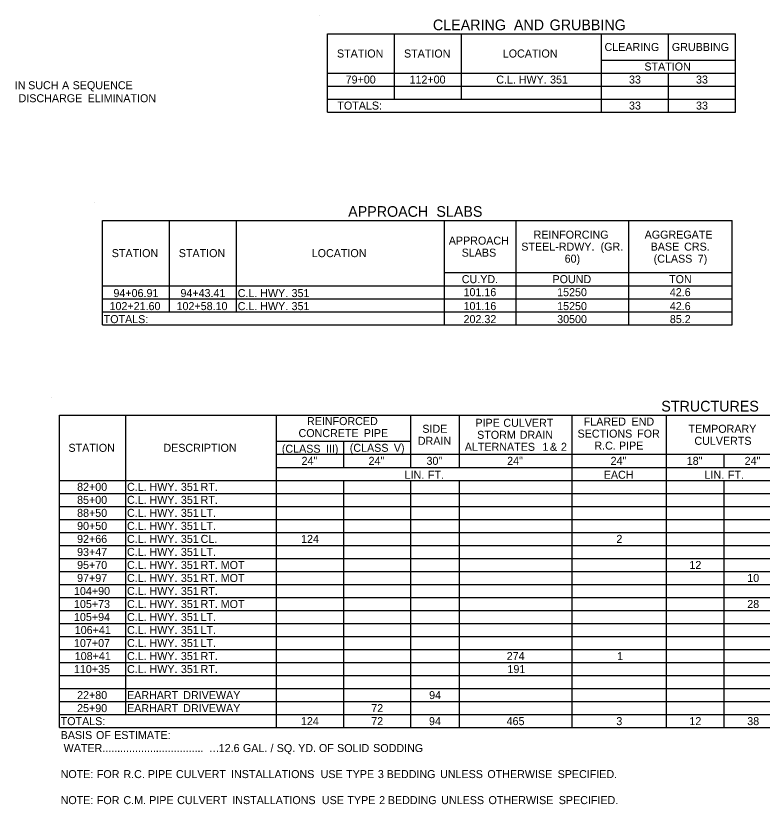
# Model space of a CAD drawing. Extents: x 1197542 to 1207068, y 230488 to 237324.
# Drawn here: x 1200309 to 1200869, y 231751 to 232342 of the extents above; entities that cross this region are included whole.
import ezdxf

# ---------------------------------------------------------------- set-up
doc = ezdxf.new("R2010")
doc.units = 0
doc.layers.add('Default', color=7, linetype='Continuous')

msp = doc.modelspace()

# ---------------------------------------------------------------- linework, layer by layer
at = {"layer": 'Default'}
for p, q in [((1200537.11, 232342.15), (1200537.11, 232342.15)), ((1200542.96, 232328.5), (1200848.62, 232328.5)), ((1200542.96, 232270), (1200542.96, 232328.5)), ((1200542.96, 232270), (1200542.96, 232328.5)), ((1200593.17, 232279.75), (1200593.17, 232328.5)), ((1200643.38, 232279.75), (1200643.38, 232328.5)), ((1200748.2, 232270), (1200748.2, 232328.5)), ((1200798.41, 232309), (1200798.41, 232328.5)), ((1200848.62, 232270), (1200848.62, 232328.5)), ((1200848.62, 232309), (1200848.62, 232328.5)), ((1200748.2, 232309), (1200848.62, 232309)), ((1200748.2, 232279.75), (1200748.2, 232309)), ((1200542.96, 232299.25), (1200848.62, 232299.25)), ((1200593.17, 232279.75), (1200593.17, 232299.25)), ((1200643.38, 232279.75), (1200643.38, 232299.25)), ((1200798.41, 232270), (1200798.41, 232299.25)), ((1200798.41, 232270), (1200798.41, 232299.25)), ((1200848.62, 232279.75), (1200848.62, 232299.25)), ((1200542.96, 232289.5), (1200848.62, 232289.5)), ((1200542.96, 232279.75), (1200848.62, 232279.75)), ((1200643.38, 232279.75), (1200848.62, 232279.75)), ((1200542.96, 232270), (1200848.62, 232270)), ((1200368.37, 232202.35), (1200368.37, 232202.35)), ((1200374.22, 232188.7), (1200846.12, 232188.7)), ((1200374.22, 232110.7), (1200374.22, 232188.7)), ((1200374.22, 232110.7), (1200374.22, 232188.7)), ((1200424.44, 232120.45), (1200424.44, 232188.7)), ((1200474.65, 232120.45), (1200474.65, 232188.7)), ((1200630.65, 232110.7), (1200630.65, 232188.7)), ((1200684.27, 232110.7), (1200684.27, 232188.7)), ((1200768.61, 232110.7), (1200768.61, 232188.7)), ((1200846.12, 232110.7), (1200846.12, 232188.7)), ((1200630.65, 232149.7), (1200846.12, 232149.7)), ((1200684.27, 232110.7), (1200684.27, 232149.7)), ((1200768.61, 232110.7), (1200768.61, 232149.7)), ((1200846.12, 232110.7), (1200846.12, 232149.7)), ((1200374.22, 232139.95), (1200846.12, 232139.95)), ((1200424.44, 232120.45), (1200424.44, 232139.95)), ((1200474.65, 232120.45), (1200474.65, 232139.95)), ((1200630.65, 232110.7), (1200630.65, 232139.95)), ((1200374.22, 232130.2), (1200846.12, 232130.2)), ((1200374.22, 232120.45), (1200846.12, 232120.45)), ((1200374.22, 232110.7), (1200846.12, 232110.7)), ((1200336.15, 232056.51), (1200336.15, 232056.51)), ((1200342, 232042.86), (1201314.56, 232042.86)), ((1200342, 231808.86), (1200342, 232042.86)), ((1200342, 231808.86), (1200342, 232042.86)), ((1200391.72, 231818.61), (1200391.72, 232042.86)), ((1200504.82, 231808.86), (1200504.82, 232042.86)), ((1200605.25, 232003.86), (1200605.25, 232042.86)), ((1200641.81, 232003.86), (1200641.81, 232042.86)), ((1200726.15, 231808.86), (1200726.15, 232042.86)), ((1200796.83, 231808.86), (1200796.83, 232042.86)), ((1200796.83, 231808.86), (1200796.83, 232042.86)), ((1200504.82, 232023.36), (1200605.25, 232023.36)), ((1200555.03, 232003.86), (1200555.03, 232023.36)), ((1200555.03, 232003.86), (1200555.03, 232023.36)), ((1200504.82, 232013.61), (1200555.03, 232013.61)), ((1200555.03, 232013.61), (1200952.35, 232013.61)), ((1200605.25, 232003.86), (1200605.25, 232013.61)), ((1200641.81, 232003.86), (1200641.81, 232013.61)), ((1200726.15, 231808.86), (1200726.15, 232013.61)), ((1200840.22, 232003.86), (1200840.22, 232013.61)), ((1200840.22, 232003.86), (1200840.22, 232013.61)), ((1200504.82, 232003.86), (1200952.35, 232003.86)), ((1200342, 231994.11), (1201314.56, 231994.11)), ((1200391.72, 231818.61), (1200391.72, 231994.11)), ((1200555.03, 231808.86), (1200555.03, 231994.11)), ((1200555.03, 231808.86), (1200555.03, 231994.11)), ((1200605.25, 231808.86), (1200605.25, 231994.11)), ((1200605.25, 231808.86), (1200605.25, 231994.11)), ((1200641.81, 231808.86), (1200641.81, 231994.11)), ((1200641.81, 231808.86), (1200641.81, 231994.11)), ((1200840.22, 231808.86), (1200840.22, 231994.11)), ((1200840.22, 231808.86), (1200840.22, 231994.11)), ((1200342, 231984.36), (1201314.56, 231984.36)), ((1200342, 231974.61), (1201314.56, 231974.61)), ((1200342, 231964.86), (1201314.56, 231964.86)), ((1200342, 231955.11), (1201314.56, 231955.11)), ((1200342, 231945.36), (1201314.56, 231945.36)), ((1200342, 231935.61), (1201314.56, 231935.61)), ((1200342, 231925.86), (1201314.56, 231925.86)), ((1200342, 231916.11), (1201314.56, 231916.11)), ((1200342, 231906.36), (1201314.56, 231906.36)), ((1200342, 231896.61), (1201314.56, 231896.61)), ((1200342, 231886.86), (1201314.56, 231886.86)), ((1200342, 231877.11), (1201314.56, 231877.11)), ((1200342, 231867.36), (1201314.56, 231867.36)), ((1200342, 231857.61), (1201314.56, 231857.61)), ((1200342, 231847.86), (1201314.56, 231847.86)), ((1200342, 231838.11), (1201314.56, 231838.11)), ((1200342, 231828.36), (1201314.56, 231828.36)), ((1200342, 231818.61), (1201101.52, 231818.61)), ((1200342, 231818.61), (1200504.82, 231818.61)), ((1200342, 231808.86), (1201314.56, 231808.86))]:
    msp.add_line(p, q, dxfattribs=at)

# ---------------------------------------------------------------- texts
for s, height, p in [('CLEARING', 8, (1200621.91, 232331.33)), (' AND', 8, (1200679.61, 232331.33)), (' GRUBBING', 8, (1200706.38, 232331.33)), ('CLEARING', 6, (1200750.5, 232315.75)), ('GRUBBING', 6, (1200800.95, 232315.75)), ('STATION', 6, (1200550, 232310.88)), ('STATION', 6, (1200600.22, 232310.88)), ('LOCATION', 6, (1200674.24, 232310.88)), ('STATION', 6, (1200780.35, 232301.13)), ('79+00', 6, (1200556.5, 232291.38)), ('112+00', 6, (1200604.38, 232291.38)), ('C.L.', 6, (1200669.35, 232291.38)), (' HWY.', 6, (1200683.98, 232291.38)), (' 351', 6, (1200707.47, 232291.38)), ('33', 6, (1200768.83, 232291.38)), ('33', 6, (1200819.04, 232291.38)), (' IN', 6, (1200306.36, 232287.11)), (' SUCH', 6, (1200316.38, 232287.11)), (' A', 6, (1200341.79, 232287.11)), (' SEQUENCE', 6, (1200349.73, 232287.11)), (' DISCHARGE', 6, (1200309.22, 232277.36)), (' ELIMINATION', 6, (1200360.95, 232277.36)), ('TOTALS:', 6, (1200550.31, 232271.88)), ('33', 6, (1200768.82, 232271.88)), ('33', 6, (1200819.04, 232271.88)), ('APPROACH', 8, (1200558.39, 232191.53)), (' SLABS', 8, (1200621.51, 232191.53)), ('REINFORCING', 6, (1200697.35, 232175.2)), ('AGGREGATE', 6, (1200780.56, 232175.2)), ('APPROACH', 6, (1200633.79, 232170.7)), ('STEEL-RDWY.', 6, (1200688.13, 232166.2)), (' (GR.', 6, (1200745.31, 232166.2)), ('BASE', 6, (1200785.04, 232166.2)), (' CRS.', 6, (1200807.92, 232166.2)), ('STATION', 6, (1200381.27, 232161.33)), ('STATION', 6, (1200431.48, 232161.33)), ('LOCATION', 6, (1200531.1, 232161.33)), ('SLABS', 6, (1200643.46, 232161.7)), ('60)', 6, (1200720.61, 232157.2)), ('(CLASS', 6, (1200787.3, 232157.2)), (' 7)', 6, (1200818.09, 232157.2)), ('CU.YD.', 6, (1200643.54, 232141.83)), ('POUND', 6, (1200711.51, 232141.83)), ('TON', 6, (1200798.86, 232141.83)), ('94+06.91', 6, (1200382.51, 232131.4)), ('94+43.41', 6, (1200432.72, 232131.4)), ('C.L.', 6, (1200475.62, 232131.4)), (' HWY.', 6, (1200490.26, 232131.4)), (' 351', 6, (1200513.75, 232131.4)), ('101.16', 6, (1200644.84, 232132.08)), ('15250', 6, (1200714.99, 232132.08)), ('42.6', 6, (1200799.4, 232132.08)), ('102+21.60', 6, (1200379.61, 232121.65)), ('102+58.10', 6, (1200429.82, 232121.65)), ('C.L.', 6, (1200475.62, 232121.65)), (' HWY.', 6, (1200490.26, 232121.65)), (' 351', 6, (1200513.75, 232121.65)), ('101.16', 6, (1200644.84, 232121.65)), ('15250', 6, (1200714.99, 232121.65)), ('42.6', 6, (1200799.4, 232121.65)), ('TOTALS:', 6, (1200375.2, 232111.9)), ('202.32', 6, (1200644.86, 232111.9)), ('30500', 6, (1200715, 232111.9)), ('85.2', 6, (1200799.43, 232111.9)), ('STRUCTURES', 8, (1200793.03, 232045.68)), ('REINFORCED', 6, (1200527.53, 232035.51)), ('PIPE', 6, (1200653.76, 232034.23)), (' CULVERT', 6, (1200672.45, 232034.23)), ('FLARED', 6, (1200734.89, 232035.13)), (' END', 6, (1200768.47, 232035.13)), ('CONCRETE', 6, (1200521.21, 232026.51)), (' PIPE', 6, (1200567.84, 232026.51)), ('SIDE', 6, (1200613.95, 232029.73)), ('STORM', 6, (1200655.04, 232025.23)), (' DRAIN', 6, (1200684.71, 232025.23)), ('SECTIONS', 6, (1200730.27, 232026.13)), (' FOR', 6, (1200772.72, 232026.13)), ('TEMPORARY', 6, (1200813.43, 232029.73)), ('DRAIN', 6, (1200610.59, 232020.73)), ('CULVERTS', 6, (1200817.83, 232020.73)), ('STATION', 6, (1200348.8, 232015.48)), ('DESCRIPTION', 6, (1200419.96, 232015.48)), ('(CLASS', 6, (1200508.7, 232014.81)), (' III)', 6, (1200539.49, 232014.81)), ('(CLASS', 6, (1200559.6, 232015.48)), (' V)', 6, (1200590.4, 232015.48)), ('ALTERNATES', 6, (1200645.78, 232016.23)), (' 1', 6, (1200701.73, 232016.23)), (' &', 6, (1200707.36, 232016.23)), (' 2', 6, (1200715.61, 232016.23)), ('R.C.', 6, (1200742.89, 232017.13)), (' PIPE', 6, (1200759.07, 232017.13)), ('24"', 6, (1200523.49, 232005.73)), ('24"', 6, (1200573.7, 232005.73)), ('30"', 6, (1200617.09, 232005.73)), ('24"', 6, (1200677.54, 232005.73)), ('24"', 6, (1200755.05, 232005.73)), ('18"', 6, (1200812.09, 232005.73)), ('24"', 6, (1200855.48, 232005.73)), ('LIN.', 6, (1200600.69, 231995.31)), (' FT.', 6, (1200615.95, 231995.31)), ('EACH', 6, (1200749.93, 231995.31)), ('LIN.', 6, (1200825.43, 231995.31)), (' FT.', 6, (1200840.69, 231995.31)), ('82+00', 6, (1200355.29, 231986.23)), ('C.L.', 6, (1200392.7, 231986.23)), (' HWY.', 6, (1200407.33, 231986.23)), (' 351', 6, (1200430.82, 231986.23)), (' RT.', 6, (1200445.58, 231986.23)), ('85+00', 6, (1200355.29, 231976.48)), ('C.L.', 6, (1200392.7, 231976.48)), (' HWY.', 6, (1200407.33, 231976.48)), (' 351', 6, (1200430.82, 231976.48)), (' RT.', 6, (1200445.58, 231976.48)), ('88+50', 6, (1200355.29, 231966.73)), ('C.L.', 6, (1200392.7, 231966.73)), (' HWY.', 6, (1200407.33, 231966.73)), (' 351', 6, (1200430.82, 231966.73)), (' LT.', 6, (1200445.58, 231966.73)), ('90+50', 6, (1200355.29, 231956.98)), ('C.L.', 6, (1200392.7, 231956.98)), (' HWY.', 6, (1200407.33, 231956.98)), (' 351', 6, (1200430.82, 231956.98)), (' LT.', 6, (1200445.58, 231956.98)), ('92+66', 6, (1200355.28, 231947.23)), ('C.L.', 6, (1200392.7, 231947.23)), (' HWY.', 6, (1200407.33, 231947.23)), (' 351', 6, (1200430.82, 231947.23)), (' CL.', 6, (1200445.58, 231947.23)), ('124', 6, (1200523.14, 231947.23)), ('2', 6, (1200759.38, 231947.23)), ('93+47', 6, (1200355.28, 231937.48)), ('C.L.', 6, (1200392.7, 231937.48)), (' HWY.', 6, (1200407.33, 231937.48)), (' 351', 6, (1200430.82, 231937.48)), (' LT.', 6, (1200445.58, 231937.48)), ('95+70', 6, (1200355.29, 231927.73)), ('C.L.', 6, (1200392.7, 231927.73)), (' HWY.', 6, (1200407.33, 231927.73)), (' 351', 6, (1200430.82, 231927.73)), (' RT.', 6, (1200445.58, 231927.73)), (' MOT', 6, (1200460.68, 231927.73)), ('12', 6, (1200814.09, 231927.73)), ('97+97', 6, (1200355.28, 231917.98)), ('C.L.', 6, (1200392.7, 231917.98)), (' HWY.', 6, (1200407.33, 231917.98)), (' 351', 6, (1200430.82, 231917.98)), (' RT.', 6, (1200445.58, 231917.98)), (' MOT', 6, (1200460.68, 231917.98)), ('10', 6, (1200857.46, 231917.98)), ('104+90', 6, (1200352.96, 231908.23)), ('C.L.', 6, (1200392.7, 231908.23)), (' HWY.', 6, (1200407.33, 231908.23)), (' 351', 6, (1200430.82, 231908.23)), (' RT.', 6, (1200445.58, 231908.23)), ('105+73', 6, (1200352.95, 231898.48)), ('C.L.', 6, (1200392.7, 231898.48)), (' HWY.', 6, (1200407.33, 231898.48)), (' 351', 6, (1200430.82, 231898.48)), (' RT.', 6, (1200445.58, 231898.48)), (' MOT', 6, (1200460.68, 231898.48)), ('28', 6, (1200857.44, 231898.48)), ('105+94', 6, (1200352.96, 231888.73)), ('C.L.', 6, (1200392.7, 231888.73)), (' HWY.', 6, (1200407.33, 231888.73)), (' 351', 6, (1200430.82, 231888.73)), (' LT.', 6, (1200445.58, 231888.73)), ('106+41', 6, (1200353.53, 231878.98)), ('C.L.', 6, (1200392.7, 231878.98)), (' HWY.', 6, (1200407.33, 231878.98)), (' 351', 6, (1200430.82, 231878.98)), (' LT.', 6, (1200445.58, 231878.98)), ('107+07', 6, (1200352.95, 231869.23)), ('C.L.', 6, (1200392.7, 231869.23)), (' HWY.', 6, (1200407.33, 231869.23)), (' 351', 6, (1200430.82, 231869.23)), (' LT.', 6, (1200445.58, 231869.23)), ('108+41', 6, (1200353.53, 231859.48)), ('C.L.', 6, (1200392.7, 231859.48)), (' HWY.', 6, (1200407.33, 231859.48)), (' 351', 6, (1200430.82, 231859.48)), (' RT.', 6, (1200445.58, 231859.48)), ('274', 6, (1200677.19, 231859.48)), ('1', 6, (1200759.93, 231859.48)), ('110+35', 6, (1200352.93, 231849.73)), ('C.L.', 6, (1200392.7, 231849.73)), (' HWY.', 6, (1200407.33, 231849.73)), (' 351', 6, (1200430.82, 231849.73)), (' RT.', 6, (1200445.58, 231849.73)), ('191', 6, (1200677.76, 231849.73)), ('22+80', 6, (1200355.29, 231830.23)), ('EARHART', 6, (1200392.7, 231830.23)), (' DRIVEWAY', 6, (1200432.59, 231830.23)), ('94', 6, (1200619.07, 231830.23)), ('25+90', 6, (1200355.29, 231820.48)), ('EARHART', 6, (1200392.7, 231820.48)), (' DRIVEWAY', 6, (1200432.59, 231820.48)), ('72', 6, (1200575.7, 231820.48)), ('TOTALS:', 6, (1200342.97, 231810.73)), ('124', 6, (1200523.03, 231810.73)), ('72', 6, (1200575.69, 231810.73)), ('94', 6, (1200618.96, 231810.73)), ('465', 6, (1200677.11, 231810.73)), ('3', 6, (1200759.34, 231810.73)), ('12', 6, (1200814.08, 231810.73)), ('38', 6, (1200857.44, 231810.73)), ('BASIS', 6, (1200342.97, 231800.31)), (' OF', 6, (1200367.23, 231800.31)), (' ESTIMATE:', 6, (1200380.82, 231800.31)), (' WATER..................................', 6, (1200342.97, 231790.56)), ('12.6', 6, (1200461.38, 231790.56)), (' GAL.', 6, (1200477.31, 231790.56)), (' /', 6, (1200498.01, 231790.56)), (' SQ.', 6, (1200502.67, 231790.56)), (' YD.', 6, (1200518.71, 231790.56)), (' OF', 6, (1200534.28, 231790.56)), (' SOLID', 6, (1200547.87, 231790.56)), (' SODDING', 6, (1200574.9, 231790.56)), ('…', 6, (1200453.98, 231790.56)), ('NOTE:', 6, (1200342.97, 231771.06)), (' FOR', 6, (1200367.86, 231771.06)), (' R.C.', 6, (1200387.77, 231771.06)), (' PIPE', 6, (1200406.13, 231771.06)), (' CULVERT', 6, (1200427.12, 231771.06)), (' INSTALLATIONS', 6, (1200468.41, 231771.06)), (' USE', 6, (1200535.52, 231771.06)), (' TYPE', 6, (1200554.64, 231771.06)), (' 3', 6, (1200578.42, 231771.06)), (' BEDDING', 6, (1200585.03, 231771.06)), (' UNLESS', 6, (1200625.03, 231771.06)), (' OTHERWISE', 6, (1200660.47, 231771.06)), (' SPECIFIED.', 6, (1200713.12, 231771.06)), ('NOTE:', 6, (1200342.97, 231751.56)), (' FOR', 6, (1200367.86, 231751.56)), (' C.M.', 6, (1200387.77, 231751.56)), (' PIPE', 6, (1200407.06, 231751.56)), (' CULVERT', 6, (1200428.05, 231751.56)), (' INSTALLATIONS', 6, (1200469.34, 231751.56)), (' USE', 6, (1200536.45, 231751.56)), (' TYPE', 6, (1200555.57, 231751.56)), (' 2', 6, (1200579.35, 231751.56)), (' BEDDING', 6, (1200585.89, 231751.56)), (' UNLESS', 6, (1200625.89, 231751.56)), (' OTHERWISE', 6, (1200661.33, 231751.56)), (' SPECIFIED.', 6, (1200713.98, 231751.56))]:
    msp.add_text(s, height=height, dxfattribs=at).set_placement(p)

doc.saveas('drawing.dxf')
